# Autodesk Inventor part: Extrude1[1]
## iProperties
Created: 2010-10
Part Number: Extrude1[1]
Document SubType Name: Modeling
Designer: Administrator
Density: 7.85 g/cm^3
Material: Steel
Mass: 199.921 g
Surface Area: 127.303 cm^2
Volume: 25.4676 cm^3
Author: Administrator
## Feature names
1. Base1
